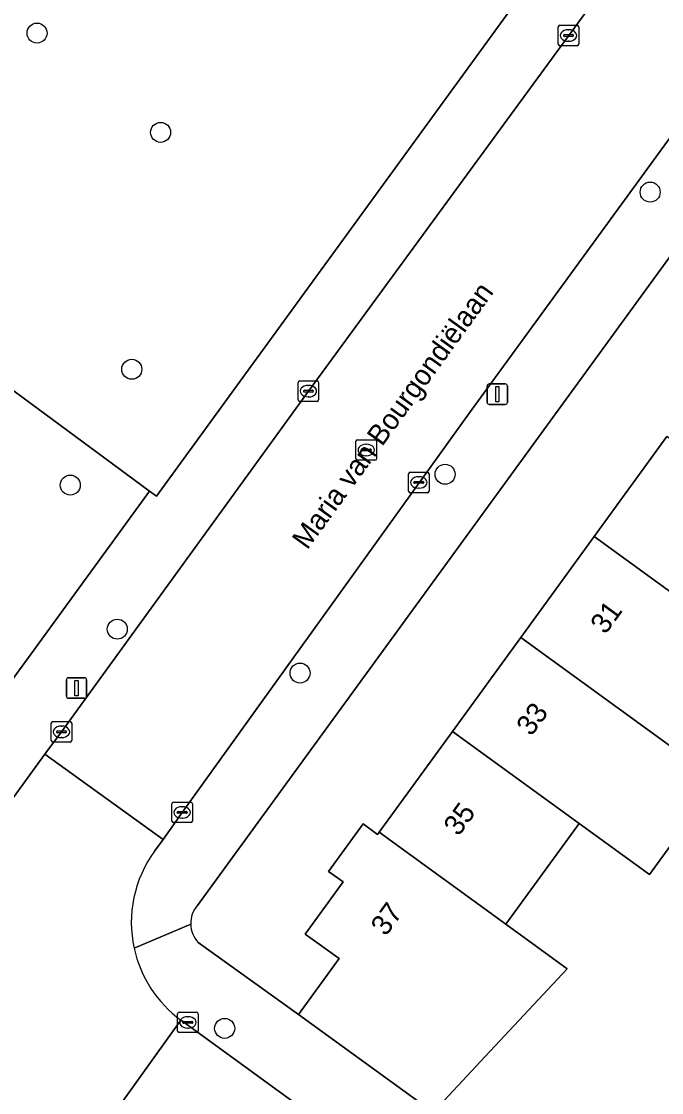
# Model space of a CAD drawing. Extents: x 159674 to 160531, y 382172 to 382904.
# Drawn here: x 160132.8 to 160164.1, y 382625.8 to 382678.2 of the extents above; entities that cross this region are included whole.
import ezdxf

# ---------------------------------------------------------------- set-up
doc = ezdxf.new("R2010")
doc.units = 0
for name, color, linetype in [('IMGEO_Boom', 7, 'Continuous'), ('IMGEO_Erf', 7, 'Continuous'), ('IMGEO_Groenvoorziening', 7, 'Continuous'), ('IMGEO_Kolk', 7, 'Continuous'), ('IMGEO_Lichtmast', 7, 'Continuous'), ('IMGEO_Openbare_ruimte_label', 7, 'Continuous'), ('IMGEO_Pand', 7, 'Continuous'), ('IMGEO_Pand_nummerreeks', 7, 'Continuous'), ('IMGEO_Rijbaan_lokaal_open', 7, 'Continuous'), ('IMGEO_Rioolput', 7, 'Continuous'), ('IMGEO_Voetpad_open', 7, 'Continuous')]:
    doc.layers.add(name, color=color, linetype=linetype)

msp = doc.modelspace()

# ---------------------------------------------------------------- linework, layer by layer
at = {"layer": 'IMGEO_Boom'}
for centre in [(160133.528, 382677.612), (160139.568, 382672.758), (160163.493, 382669.836), (160138.16, 382661.171), (160153.471, 382656.038), (160135.153, 382655.509), (160137.452, 382648.464), (160146.382, 382646.319), (160142.699, 382628.945)]:
    msp.add_circle(centre, 0.489, dxfattribs=at)
at = {"layer": 'IMGEO_Erf'}
for points in [[(160167.947, 382671.456), (160141.366, 382634.961)], [(160078.977, 382572.654), (160139.025, 382655.211), (160118.682, 382670.24), (160112.498, 382662.82), (160085.741, 382648.366)], [(160141.407, 382633.141), (160146.308, 382629.63), (160148.288, 382632.355), (160146.63, 382633.559), (160148.483, 382636.107), (160147.78, 382636.619), (160149.467, 382638.941), (160150.17, 382638.429), (160150.249, 382638.537), (160153.83, 382643.463), (160157.172, 382648.061), (160160.763, 382653.001), (160164.313, 382657.885)], [(160166.803, 382641.063), (160163.461, 382636.464), (160160.022, 382638.963), (160156.441, 382634.037), (160159.44, 382631.857), (160155.204, 382627.327), (160152.983, 382624.952)]]:
    msp.add_lwpolyline(points, dxfattribs=at)
for centre, radius, start, end in [((160142.414, 382634.072), 1.375, 139.6946, 181.2035), ((160142.413, 382634.076), 1.373, 181.3703, 222.9099)]:
    msp.add_arc(centre, radius, start, end, dxfattribs=at)
at = {"layer": 'IMGEO_Groenvoorziening'}
msp.add_lwpolyline([(160158.819, 382681.732), (160148.758, 382688.93), (160117.651, 382672.153), (160118.682, 382670.24), (160139.025, 382655.211), (160139.364, 382654.969)], close=True, dxfattribs=at)
at = {"layer": 'IMGEO_Kolk'}
for p, q in [((160159, 382677.068), (160159, 382677.92)), ((160159.075, 382677.994), (160159.927, 382677.994)), ((160160.001, 382677.92), (160160.001, 382677.068)), ((160159.259, 382677.488), (160159.259, 382677.5)), ((160159.697, 382677.451), (160159.299, 382677.451)), ((160159.302, 382677.537), (160159.7, 382677.537)), ((160159.488, 382677.774), (160159.513, 382677.774)), ((160159.743, 382677.5), (160159.743, 382677.488)), ((160159.927, 382676.994), (160159.075, 382676.994)), ((160159.511, 382677.214), (160159.486, 382677.214)), ((160146.291, 382659.678), (160146.291, 382660.53)), ((160146.366, 382660.604), (160147.218, 382660.604)), ((160147.292, 382660.53), (160147.292, 382659.678)), ((160146.55, 382660.098), (160146.55, 382660.11)), ((160146.988, 382660.061), (160146.59, 382660.061)), ((160146.593, 382660.147), (160146.991, 382660.147)), ((160146.779, 382660.384), (160146.804, 382660.384)), ((160147.034, 382660.11), (160147.034, 382660.098)), ((160147.218, 382659.604), (160146.366, 382659.604)), ((160146.802, 382659.824), (160146.777, 382659.824)), ((160151.686, 382655.213), (160151.686, 382656.065)), ((160151.761, 382656.139), (160152.613, 382656.139)), ((160152.174, 382655.919), (160152.199, 382655.919)), ((160152.687, 382656.065), (160152.687, 382655.213)), ((160151.945, 382655.633), (160151.945, 382655.645)), ((160152.383, 382655.596), (160151.985, 382655.596)), ((160151.988, 382655.682), (160152.386, 382655.682)), ((160152.197, 382655.359), (160152.172, 382655.359)), ((160152.429, 382655.645), (160152.429, 382655.633)), ((160152.613, 382655.139), (160151.761, 382655.139)), ((160134.222, 382643.019), (160134.222, 382643.871)), ((160134.297, 382643.945), (160135.149, 382643.945)), ((160135.223, 382643.871), (160135.223, 382643.019)), ((160134.481, 382643.439), (160134.481, 382643.451)), ((160134.919, 382643.402), (160134.521, 382643.402)), ((160134.524, 382643.488), (160134.922, 382643.488)), ((160134.71, 382643.725), (160134.735, 382643.725)), ((160134.965, 382643.451), (160134.965, 382643.439)), ((160135.149, 382642.945), (160134.297, 382642.945)), ((160134.733, 382643.165), (160134.708, 382643.165)), ((160140.119, 382639.079), (160140.119, 382639.931)), ((160140.194, 382640.005), (160141.046, 382640.005)), ((160140.421, 382639.548), (160140.819, 382639.548)), ((160140.607, 382639.785), (160140.632, 382639.785)), ((160141.12, 382639.931), (160141.12, 382639.079)), ((160140.378, 382639.499), (160140.378, 382639.511)), ((160140.816, 382639.462), (160140.418, 382639.462)), ((160140.63, 382639.225), (160140.605, 382639.225)), ((160140.862, 382639.511), (160140.862, 382639.499)), ((160141.046, 382639.005), (160140.194, 382639.005)), ((160140.4, 382628.811), (160140.4, 382629.663)), ((160140.475, 382629.737), (160141.327, 382629.737)), ((160141.401, 382629.663), (160141.401, 382628.811)), ((160140.659, 382629.231), (160140.659, 382629.243)), ((160141.097, 382629.194), (160140.699, 382629.194)), ((160140.702, 382629.28), (160141.1, 382629.28)), ((160140.888, 382629.517), (160140.913, 382629.517)), ((160141.143, 382629.243), (160141.143, 382629.231)), ((160141.327, 382628.737), (160140.475, 382628.737)), ((160140.911, 382628.957), (160140.886, 382628.957))]:
    msp.add_line(p, q, dxfattribs=at)
for points in [[(160159, 382677.068), (160159, 382677.92)], [(160159.075, 382677.994), (160159.927, 382677.994)], [(160160.001, 382677.92), (160160.001, 382677.068)], [(160159.927, 382676.994), (160159.075, 382676.994)], [(160146.291, 382659.678), (160146.291, 382660.53)], [(160146.366, 382660.604), (160147.218, 382660.604)], [(160147.292, 382660.53), (160147.292, 382659.678)], [(160147.218, 382659.604), (160146.366, 382659.604)], [(160151.686, 382655.213), (160151.686, 382656.065)], [(160151.761, 382656.139), (160152.613, 382656.139)], [(160152.687, 382656.065), (160152.687, 382655.213)], [(160152.613, 382655.139), (160151.761, 382655.139)], [(160134.222, 382643.019), (160134.222, 382643.871)], [(160134.297, 382643.945), (160135.149, 382643.945)], [(160135.223, 382643.871), (160135.223, 382643.019)], [(160135.149, 382642.945), (160134.297, 382642.945)], [(160140.119, 382639.079), (160140.119, 382639.931)], [(160140.194, 382640.005), (160141.046, 382640.005)], [(160141.12, 382639.931), (160141.12, 382639.079)], [(160141.046, 382639.005), (160140.194, 382639.005)], [(160140.4, 382628.811), (160140.4, 382629.663)], [(160140.475, 382629.737), (160141.327, 382629.737)], [(160141.401, 382629.663), (160141.401, 382628.811)], [(160141.327, 382628.737), (160140.475, 382628.737)]]:
    msp.add_lwpolyline(points, dxfattribs=at)
for centre, radius, start, end in [((160159.077, 382677.918), 0.0765, 91.552, 178.448), ((160159.077, 382677.918), 0.0765, 91.552, 178.448), ((160159.925, 382677.918), 0.0765, 1.552, 88.448), ((160159.925, 382677.918), 0.0765, 1.552, 88.448), ((160159.299, 382677.497), 0.0403, 85.8775, 175.7526), ((160159.296, 382677.487), 0.0366, 178.938, 274.7102), ((160159.7, 382677.494), 0.043, 264.8664, 352.4533), ((160159.704, 382677.499), 0.0386, 1.7309, 96.639), ((160159.077, 382677.07), 0.0765, 181.552, 268.448), ((160159.077, 382677.07), 0.0765, 181.552, 268.448), ((160159.925, 382677.07), 0.0765, 271.552, 358.448), ((160159.925, 382677.07), 0.0765, 271.552, 358.448), ((160146.368, 382660.528), 0.0765, 91.552, 178.448), ((160146.368, 382660.528), 0.0765, 91.552, 178.448), ((160147.216, 382660.528), 0.0765, 1.552, 88.448), ((160147.216, 382660.528), 0.0765, 1.552, 88.448), ((160146.59, 382660.107), 0.0403, 85.8775, 175.7526), ((160146.587, 382660.097), 0.0366, 178.938, 274.7102), ((160146.991, 382660.104), 0.043, 264.8664, 352.4533), ((160146.995, 382660.109), 0.0386, 1.7309, 96.639), ((160146.368, 382659.68), 0.0765, 181.552, 268.448), ((160146.368, 382659.68), 0.0765, 181.552, 268.448), ((160147.216, 382659.68), 0.0765, 271.552, 358.448), ((160147.216, 382659.68), 0.0765, 271.552, 358.448), ((160151.763, 382656.063), 0.0765, 91.552, 178.448), ((160151.763, 382656.063), 0.0765, 91.552, 178.448), ((160152.611, 382656.063), 0.0765, 1.552, 88.448), ((160152.611, 382656.063), 0.0765, 1.552, 88.448), ((160151.985, 382655.642), 0.0403, 85.8775, 175.7526), ((160151.982, 382655.632), 0.0366, 178.938, 274.7102), ((160152.386, 382655.639), 0.043, 264.8664, 352.4533), ((160152.39, 382655.644), 0.0386, 1.7309, 96.639), ((160151.763, 382655.215), 0.0765, 181.552, 268.448), ((160151.763, 382655.215), 0.0765, 181.552, 268.448), ((160152.611, 382655.215), 0.0765, 271.552, 358.448), ((160152.611, 382655.215), 0.0765, 271.552, 358.448), ((160134.299, 382643.869), 0.0765, 91.552, 178.448), ((160134.299, 382643.869), 0.0765, 91.552, 178.448), ((160135.147, 382643.869), 0.0765, 1.552, 88.448), ((160135.147, 382643.869), 0.0765, 1.552, 88.448), ((160134.521, 382643.448), 0.0403, 85.8775, 175.7526), ((160134.518, 382643.438), 0.0366, 178.938, 274.7102), ((160134.922, 382643.445), 0.043, 264.8664, 352.4533), ((160134.926, 382643.45), 0.0386, 1.7309, 96.639), ((160134.299, 382643.021), 0.0765, 181.552, 268.448), ((160134.299, 382643.021), 0.0765, 181.552, 268.448), ((160135.147, 382643.021), 0.0765, 271.552, 358.448), ((160135.147, 382643.021), 0.0765, 271.552, 358.448), ((160140.196, 382639.929), 0.0765, 91.552, 178.448), ((160140.196, 382639.929), 0.0765, 91.552, 178.448), ((160140.418, 382639.508), 0.0403, 85.8775, 175.7526), ((160140.823, 382639.51), 0.0386, 1.7309, 96.639), ((160141.044, 382639.929), 0.0765, 1.552, 88.448), ((160141.044, 382639.929), 0.0765, 1.552, 88.448), ((160140.196, 382639.081), 0.0765, 181.552, 268.448), ((160140.196, 382639.081), 0.0765, 181.552, 268.448), ((160140.415, 382639.498), 0.0366, 178.938, 274.7102), ((160140.819, 382639.505), 0.043, 264.8664, 352.4533), ((160141.044, 382639.081), 0.0765, 271.552, 358.448), ((160141.044, 382639.081), 0.0765, 271.552, 358.448), ((160140.477, 382629.661), 0.0765, 91.552, 178.448), ((160140.477, 382629.661), 0.0765, 91.552, 178.448), ((160141.325, 382629.661), 0.0765, 1.552, 88.448), ((160141.325, 382629.661), 0.0765, 1.552, 88.448), ((160140.699, 382629.24), 0.0403, 85.8775, 175.7526), ((160140.696, 382629.23), 0.0366, 178.938, 274.7102), ((160141.1, 382629.237), 0.043, 264.8664, 352.4533), ((160141.104, 382629.242), 0.0386, 1.7309, 96.639), ((160140.477, 382628.813), 0.0765, 181.552, 268.448), ((160140.477, 382628.813), 0.0765, 181.552, 268.448), ((160141.325, 382628.813), 0.0765, 271.552, 358.448), ((160141.325, 382628.813), 0.0765, 271.552, 358.448)]:
    msp.add_arc(centre, radius, start, end, dxfattribs=at)
for centre, major_axis, ratio, start_param, end_param in [((160159.487, 382677.494), (-0.387, 0.002), 0.722429, 4.712389, 7.853982), ((160159.512, 382677.494), (-0.39, 0.002), 0.717154, 1.570796, 4.712389), ((160146.778, 382660.104), (-0.387, 0.002), 0.722429, 4.712389, 7.853982), ((160146.803, 382660.104), (-0.39, 0.002), 0.717154, 1.570796, 4.712389), ((160152.173, 382655.639), (-0.387, 0.002), 0.722429, 4.712389, 7.853982), ((160152.198, 382655.639), (-0.39, 0.002), 0.717154, 1.570796, 4.712389), ((160134.709, 382643.445), (-0.387, 0.002), 0.722429, 4.712389, 7.853982), ((160134.734, 382643.445), (-0.39, 0.002), 0.717154, 1.570796, 4.712389), ((160140.606, 382639.505), (-0.387, 0.002), 0.722429, 4.712389, 7.853982), ((160140.631, 382639.505), (-0.39, 0.002), 0.717154, 1.570796, 4.712389), ((160140.887, 382629.237), (-0.387, 0.002), 0.722429, 4.712389, 7.853982), ((160140.912, 382629.237), (-0.39, 0.002), 0.717154, 1.570796, 4.712389)]:
    msp.add_ellipse(centre, major_axis=major_axis, ratio=ratio, start_param=start_param, end_param=end_param, dxfattribs=at)
at = {"layer": 'IMGEO_Lichtmast'}
for p, q in [((160155.524, 382659.554), (160155.524, 382660.354)), ((160155.524, 382660.354), (160155.524, 382659.554)), ((160155.624, 382660.454), (160156.414, 382660.454)), ((160156.414, 382660.454), (160155.624, 382660.454)), ((160156.514, 382660.354), (160156.514, 382659.554)), ((160156.514, 382659.554), (160156.514, 382660.354)), ((160156.414, 382659.454), (160155.624, 382659.454)), ((160155.624, 382659.454), (160156.414, 382659.454)), ((160134.964, 382645.187), (160134.964, 382645.987)), ((160134.964, 382645.987), (160134.964, 382645.187)), ((160135.064, 382646.087), (160135.854, 382646.087)), ((160135.854, 382646.087), (160135.064, 382646.087)), ((160135.954, 382645.987), (160135.954, 382645.187)), ((160135.954, 382645.187), (160135.954, 382645.987)), ((160135.854, 382645.087), (160135.064, 382645.087)), ((160135.064, 382645.087), (160135.854, 382645.087))]:
    msp.add_line(p, q, dxfattribs=at)
for points in [[(160155.944, 382660.329), (160156.094, 382660.329), (160156.094, 382659.579), (160155.944, 382659.579), (160155.944, 382660.329)], [(160135.384, 382645.962), (160135.534, 382645.962), (160135.534, 382645.212), (160135.384, 382645.212), (160135.384, 382645.962)]]:
    msp.add_lwpolyline(points, dxfattribs=at)
for centre, start, end in [((160155.624, 382660.354), 90, 180), ((160155.624, 382660.354), 90, 180), ((160156.414, 382660.354), 0, 90), ((160156.414, 382660.354), 360, 90), ((160155.624, 382659.554), 180, 270), ((160155.624, 382659.554), 180, 270), ((160156.414, 382659.554), 270, 0), ((160156.414, 382659.554), 270, 0), ((160135.064, 382645.987), 90, 180), ((160135.064, 382645.987), 90, 180), ((160135.854, 382645.987), 0, 90), ((160135.854, 382645.987), 360, 90), ((160135.064, 382645.187), 180, 270), ((160135.064, 382645.187), 180, 270), ((160135.854, 382645.187), 270, 0), ((160135.854, 382645.187), 270, 0)]:
    msp.add_arc(centre, 0.1, start, end, dxfattribs=at)
at = {"layer": 'IMGEO_Pand'}
for points in [[(160170.506, 382653.385), (160164.313, 382657.885), (160160.763, 382653.001), (160166.955, 382648.5)], [(160166.955, 382648.5), (160160.763, 382653.001), (160157.172, 382648.061), (160163.365, 382643.561), (160165.928, 382641.699), (160169.518, 382646.637)], [(160163.365, 382643.561), (160157.172, 382648.061), (160153.83, 382643.463), (160160.022, 382638.963), (160163.461, 382636.464), (160166.803, 382641.063), (160165.928, 382641.699)], [(160156.441, 382634.037), (160160.022, 382638.963), (160153.83, 382643.463), (160150.249, 382638.537)], [(160156.441, 382634.037), (160150.249, 382638.537), (160150.17, 382638.429), (160149.467, 382638.941), (160147.78, 382636.619), (160148.483, 382636.107), (160146.63, 382633.559), (160148.288, 382632.355), (160146.308, 382629.63), (160152.887, 382624.85), (160152.983, 382624.952), (160155.204, 382627.327), (160159.44, 382631.857)]]:
    msp.add_lwpolyline(points, close=True, dxfattribs=at)
at = {"layer": 'IMGEO_Rijbaan_lokaal_open'}
for points in [[(160161.775, 382680.602), (160146.792, 382660.104), (160134.723, 382643.445), (160133.916, 382642.352), (160139.698, 382638.176), (160140.62, 382639.505), (160154.667, 382659.043)], [(160154.667, 382659.043), (160165.176, 382673.46)], [(160139.276, 382637.61), (160139.698, 382638.176), (160133.916, 382642.352), (160121.569, 382625.329), (160127.333, 382621.232), (160128.048, 382622.176)], [(160136.439, 382623.587), (160140.555, 382629.351)], [(160140.763, 382629.192), (160140.555, 382629.351), (160136.439, 382623.587), (160136.712, 382623.379), (160240.412, 382548.029)], [(160245.716, 382552.786), (160140.763, 382629.192)]]:
    msp.add_lwpolyline(points, dxfattribs=at)
for centre, radius, start, end in [((160144.047, 382634.121), 5.911, 143.8218, 192.3036), ((160144.044, 382634.118), 5.907, 192.2824, 233.7998)]:
    msp.add_arc(centre, radius, start, end, dxfattribs=at)
at = {"layer": 'IMGEO_Rioolput'}
for p, q in [((160149.116, 382656.8), (160149.116, 382657.652)), ((160149.191, 382657.726), (160150.043, 382657.726)), ((160149.604, 382657.506), (160149.629, 382657.506)), ((160150.117, 382657.652), (160150.117, 382656.8)), ((160149.375, 382657.22), (160149.375, 382657.232)), ((160149.813, 382657.183), (160149.415, 382657.183)), ((160149.418, 382657.269), (160149.816, 382657.269)), ((160149.627, 382656.946), (160149.602, 382656.946)), ((160149.859, 382657.232), (160149.859, 382657.22)), ((160150.043, 382656.726), (160149.191, 382656.726))]:
    msp.add_line(p, q, dxfattribs=at)
for points in [[(160149.116, 382656.8), (160149.116, 382657.652)], [(160149.191, 382657.726), (160150.043, 382657.726)], [(160150.117, 382657.652), (160150.117, 382656.8)], [(160150.043, 382656.726), (160149.191, 382656.726)]]:
    msp.add_lwpolyline(points, dxfattribs=at)
for centre, radius, start, end in [((160149.193, 382657.65), 0.0765, 91.552, 178.448), ((160149.193, 382657.65), 0.0765, 91.552, 178.448), ((160150.041, 382657.65), 0.0765, 1.552, 88.448), ((160150.041, 382657.65), 0.0765, 1.552, 88.448), ((160149.415, 382657.229), 0.0403, 85.8775, 175.7526), ((160149.412, 382657.219), 0.0366, 178.938, 274.7102), ((160149.816, 382657.226), 0.043, 264.8664, 352.4533), ((160149.82, 382657.231), 0.0386, 1.7309, 96.639), ((160149.193, 382656.802), 0.0765, 181.552, 268.448), ((160149.193, 382656.802), 0.0765, 181.552, 268.448), ((160150.041, 382656.802), 0.0765, 271.552, 358.448), ((160150.041, 382656.802), 0.0765, 271.552, 358.448)]:
    msp.add_arc(centre, radius, start, end, dxfattribs=at)
for centre, major_axis, ratio, start_param, end_param in [((160149.603, 382657.226), (-0.387, 0.002), 0.722429, 4.712389, 7.853982), ((160149.628, 382657.226), (-0.39, 0.002), 0.717154, 1.570796, 4.712389)]:
    msp.add_ellipse(centre, major_axis=major_axis, ratio=ratio, start_param=start_param, end_param=end_param, dxfattribs=at)
at = {"layer": 'IMGEO_Voetpad_open'}
for points in [[(160160.682, 382684.114), (160158.819, 382681.732), (160139.364, 382654.969), (160139.025, 382655.211), (160078.977, 382572.654), (160073.24, 382564.766), (160076.064, 382562.694), (160076.311, 382563.035), (160084.229, 382573.928), (160097.463, 382592.089), (160109.443, 382608.67), (160121.488, 382625.214), (160121.569, 382625.329), (160133.916, 382642.352), (160134.723, 382643.445), (160146.792, 382660.104), (160161.775, 382680.602)], [(160165.176, 382673.46), (160154.667, 382659.043), (160140.62, 382639.505), (160139.698, 382638.176), (160139.276, 382637.61)], [(160141.366, 382634.961), (160167.947, 382671.456)], [(160141.04, 382634.043), (160138.272, 382632.861)], [(160138.272, 382632.861), (160141.04, 382634.043)], [(160164.421, 382617.647), (160165.277, 382618.834), (160165.83, 382619.594), (160164.668, 382620.465), (160163.351, 382618.653), (160161.857, 382618.503), (160160.579, 382619.432), (160152.983, 382624.952), (160152.887, 382624.85), (160146.308, 382629.63), (160141.407, 382633.141)], [(160140.555, 382629.351), (160140.763, 382629.192), (160245.716, 382552.786)]]:
    msp.add_lwpolyline(points, dxfattribs=at)
for centre, radius, start, end in [((160144.047, 382634.121), 5.911, 143.8218, 192.3036), ((160142.414, 382634.072), 1.375, 139.6946, 181.2035), ((160142.413, 382634.076), 1.373, 181.3703, 222.9099), ((160144.044, 382634.118), 5.907, 192.2824, 233.7998)]:
    msp.add_arc(centre, radius, start, end, dxfattribs=at)

# ---------------------------------------------------------------- texts
at = {"layer": 'IMGEO_Openbare_ruimte_label'}
msp.add_text('Maria van Bourgondiëlaan', height=1, rotation=54.1159, dxfattribs=at).set_placement((160146.733, 382652.305))
at = {"layer": 'IMGEO_Pand_nummerreeks'}
for s, rotation, p in [('31', 53.9841, (160161.305, 382648.169)), ('33', 53.9841, (160157.684, 382643.188)), ('35', 53.9858, (160154.13, 382638.297)), ('37', 53.9841, (160150.574, 382633.407))]:
    msp.add_text(s, height=1, rotation=rotation, dxfattribs=at).set_placement(p)

doc.saveas('drawing.dxf')
